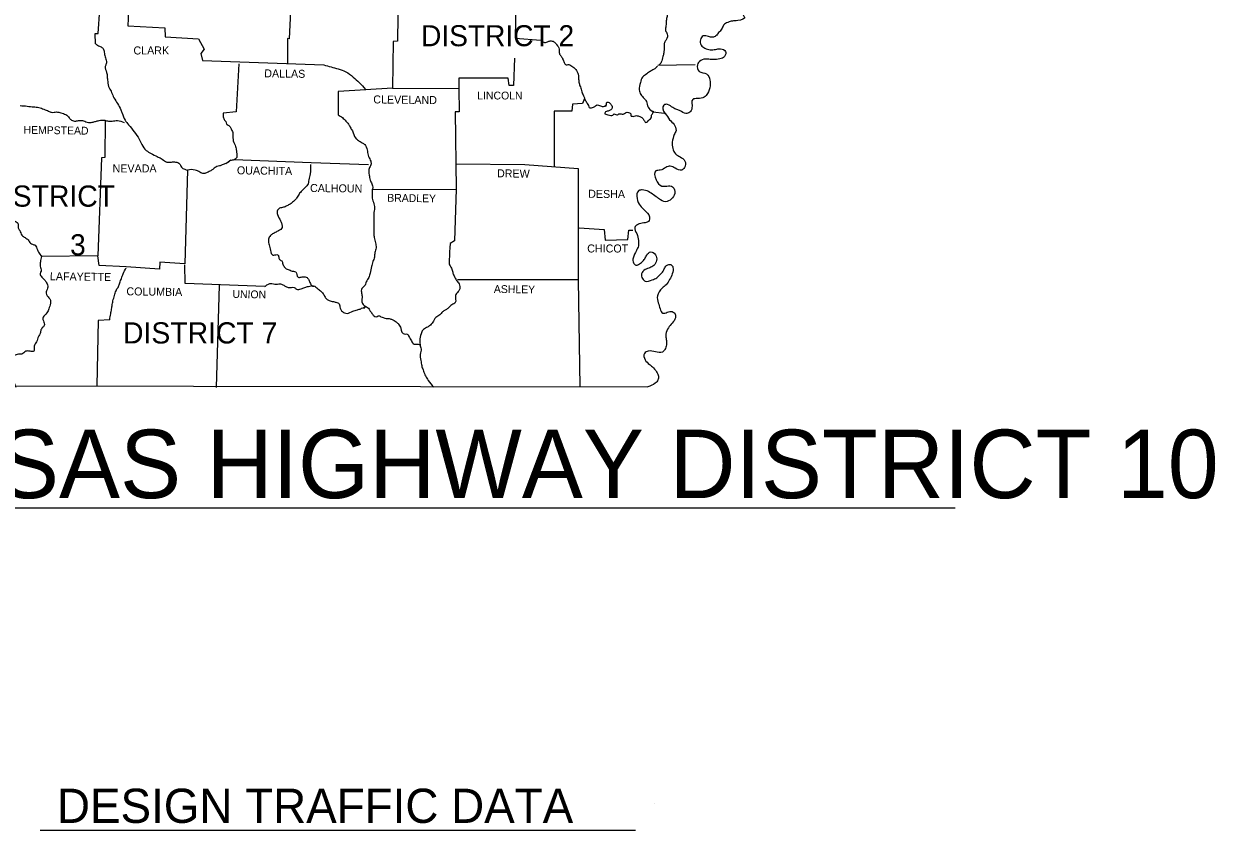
# Model space of a CAD drawing. Extents: x 152 to 3426, y 67 to 2142.
# Drawn here: x 2800 to 3426, y 1200 to 1624 of the extents above; entities that cross this region are included whole.
import ezdxf

# ---------------------------------------------------------------- set-up
doc = ezdxf.new("R2010")
doc.units = 0
for name, color, linetype in [('R_Border', 7, 'Continuous'), ('R_Grid', 7, 'Continuous'), ('S_AREA_CALC', 7, 'Continuous')]:
    doc.layers.add(name, color=color, linetype=linetype)

msp = doc.modelspace()

# ---------------------------------------------------------------- linework, layer by layer
at = {"layer": 'R_Grid'}
msp.add_line((3130.78, 1577.48), (3136.95, 1576.7), dxfattribs=at)
at = {"layer": 'S_AREA_CALC'}
for p, q in [((3133.42, 1601.94), (3152.99, 1602.24)), ((2625.16, 1369.37), (3289.7, 1369.37)), ((3131.43, 1213.84), (3131.43, 1213.84)), ((2808.55, 1199.86), (3121.64, 1199.86))]:
    msp.add_line(p, q, dxfattribs=at)
for points in [[(2997.03, 1654.09), (2996.45, 1614.56), (2994.2, 1614.47), (2993.9, 1589.91)], [(3059.06, 1653.99), (3058.28, 1616.13), (3071.88, 1615.05)], [(2940.68, 1641.37), (2939.5, 1615.74), (2938.62, 1616.03), (2938.72, 1602.72)], [(2837.65, 1613.19), (2837.46, 1618.57), (2839.02, 1618.67), (2840, 1631.29), (2855.07, 1630.32), (2854.68, 1622.59), (2874.15, 1621.51), (2874.24, 1616.81), (2891.85, 1615.74), (2894.89, 1610.45), (2893.03, 1608.11), (2893.91, 1604.49), (2957.7, 1602.14)], [(3057.99, 1605.66), (3057.4, 1591.28), (3055.15, 1591.28), (3054.76, 1595.09), (3028.73, 1595.09), (3028.73, 1589.61)], [(2913.09, 1602.63), (2911.62, 1577.48), (2904.87, 1576.7)], [(2979.81, 1589.03), (2965.33, 1588.15), (2965.24, 1575.92)], [(2993.9, 1589.91), (2979.62, 1589.03)], [(2993.9, 1589.91), (3028.54, 1589.71)], [(3028.73, 1589.71), (3028.83, 1577.48), (3026.78, 1577.38), (3027.36, 1536.78)], [(3094.87, 1584.53), (3093.7, 1581.88), (3088.51, 1581.4), (3088.22, 1577.87), (3078.93, 1577.87), (3078.83, 1548.62)], [(3105.83, 1580.22), (3106.13, 1580.51), (3106.42, 1580.81), (3106.42, 1580.81)], [(2842.84, 1572.98), (2842.64, 1553.51), (2840.88, 1553.31), (2838.92, 1501.75)], [(2910.64, 1552.34), (2951.15, 1550.87), (2981.18, 1549.69)], [(3027.07, 1550.09), (3063.37, 1549.79), (3091.55, 1547.64)], [(3091.55, 1547.64), (3091.55, 1489.13), (3092.33, 1432.87)], [(2885.98, 1546.86), (2884.71, 1497.55), (2871.5, 1498.43), (2871.41, 1494.81), (2853.79, 1495.88)], [(2983.14, 1536.68), (3027.36, 1536.78)], [(3027.36, 1536.78), (3026.39, 1509.58), (3024.23, 1508.21)], [(3092.04, 1516.43), (3105.15, 1515.65), (3105.73, 1509.97), (3117.57, 1510.36), (3118.06, 1515.16), (3120.31, 1515.16)], [(2769.26, 1512.61), (2769.46, 1433.46), (3128.04, 1432.87)], [(2853.79, 1495.88), (2839.61, 1496.67), (2838.92, 1501.75), (2809.28, 1501.46)], [(2926.69, 1485.61), (2884.91, 1487.17), (2884.71, 1497.06)], [(2902.72, 1486.29), (2901.15, 1432.58)], [(3027.95, 1489.23), (3091.55, 1489.23)], [(2845.18, 1468.19), (2839.12, 1467.8), (2838.43, 1433.36)]]:
    msp.add_lwpolyline(points, dxfattribs=at)
for points in [[(3210.42, 1697.14), (3208.17, 1694.3), (3204.85, 1696.06), (3204.85, 1698.41), (3205.34, 1700.86), (3204.16, 1702.42), (3202.11, 1701.74), (3202.11, 1698.71), (3201.91, 1695.77), (3201.32, 1691.56), (3202.69, 1690.29), (3205.83, 1689.9), (3208.08, 1689.31), (3209.45, 1687.06), (3209.35, 1684.32), (3208.27, 1681.68), (3206.71, 1679.53), (3204.26, 1678.75), (3202.3, 1680.02), (3201.52, 1682.56), (3200.64, 1684.81), (3198.98, 1686.48), (3197.22, 1684.62), (3196.82, 1681.19), (3196.92, 1678.26), (3196.92, 1674.25), (3199.47, 1671.6), (3201.03, 1668.57), (3200.54, 1665.83), (3198.68, 1662.6), (3197.9, 1659.77), (3197.12, 1655.95), (3197.22, 1651.74), (3196.53, 1647.63), (3195.16, 1644.89), (3192.62, 1642.64), (3190.95, 1641.18), (3189.58, 1639.71), (3188.9, 1636.77), (3188.41, 1634.72), (3186.55, 1632.27), (3185.08, 1632.08), (3183.91, 1633.05), (3183.52, 1634.72), (3183.52, 1636.38), (3182.74, 1638.04), (3180.29, 1638.73), (3178.33, 1638.63), (3177.45, 1637.26), (3178.72, 1633.45), (3179.21, 1631), (3178.53, 1627.67), (3178.92, 1627.28), (3175.4, 1625.42), (3172.56, 1625.13), (3170.21, 1624.44), (3167.96, 1622.98), (3166.88, 1620.82), (3165.32, 1619.06), (3163.95, 1617.4), (3162.09, 1616.62), (3160.04, 1617.01), (3157.3, 1617.3), (3155.73, 1615.35), (3156.22, 1612.51), (3158.08, 1610.85), (3160.82, 1610.06), (3163.66, 1610.26), (3166.4, 1610.55), (3168.94, 1609.18), (3168.45, 1606.54), (3166, 1605.27), (3162.38, 1604.88), (3159.45, 1605.17), (3155.93, 1604.39), (3154.17, 1602.14), (3155.14, 1598.71), (3158.96, 1597.34), (3160.72, 1594.11), (3160.82, 1591.08), (3159.55, 1587.07), (3157.79, 1585.21), (3154.36, 1584.43), (3151.72, 1583.94), (3151.33, 1579.44), (3150.15, 1577.19), (3148.1, 1576.5), (3145.16, 1577.97), (3143.4, 1578.66), (3141.25, 1579.63), (3138.51, 1581.3), (3136.46, 1581), (3137.04, 1576.7), (3137.24, 1576.5), (3139.59, 1573.27), (3141.94, 1570.73), (3143.01, 1567.7)], [(3109.06, 1665.64), (3109.35, 1661.62), (3111.7, 1661.04), (3112.68, 1659.96), (3113.17, 1657.71), (3114.83, 1656.73), (3117.08, 1655.36), (3118.45, 1654.38), (3119.43, 1652.82), (3120.02, 1650.27), (3121.58, 1648.61), (3123.74, 1647.83), (3125.3, 1645.97), (3126.28, 1643.33), (3127.85, 1642.15), (3129.41, 1640.1), (3130.19, 1639.22), (3131.56, 1636.87), (3132.93, 1635.7), (3133.91, 1635.01), (3135.48, 1634.52), (3137.43, 1633.25), (3138.71, 1631.29), (3138.71, 1629.83), (3138.22, 1627.58), (3137.83, 1625.23), (3137.63, 1622.59), (3137.43, 1620.24), (3138.32, 1618.28), (3137.83, 1615.35), (3136.85, 1613.78), (3136.75, 1611.63), (3136.46, 1608.4), (3136.07, 1606.54), (3135.18, 1603.51), (3133.91, 1601.94)], [(2837.65, 1613.19), (2839.22, 1612.21), (2841.08, 1611.33), (2842.05, 1609.87), (2842.45, 1607.62), (2843.13, 1605.17), (2843.33, 1602.63), (2842.74, 1601.26), (2843.52, 1598.13), (2843.82, 1595.97), (2844.11, 1593.43), (2844.89, 1590.01), (2846.16, 1587.66), (2847.34, 1584.82), (2849.29, 1581.79), (2850.96, 1578.46), (2851.74, 1576.7), (2853.21, 1573.08), (2855.07, 1570.63), (2858, 1566.91), (2860.64, 1563.1), (2862.11, 1560.26), (2864.36, 1557.13), (2866.91, 1555.57), (2870.13, 1553.9), (2872.19, 1552.92), (2874.54, 1551.26), (2877.57, 1551.06), (2879.82, 1551.06), (2881.88, 1550.18), (2882.85, 1548.42), (2884.61, 1547.25), (2885.98, 1546.86)], [(3071.88, 1615.05), (3073.35, 1614.07), (3075.4, 1614.17), (3076.77, 1614.76), (3077.85, 1614.66), (3079.32, 1613.78), (3080.3, 1612.61), (3080.98, 1611.73), (3081.47, 1610.36), (3081.47, 1609.08), (3081.96, 1607.32), (3082.55, 1606.64), (3083.33, 1605.37), (3083.82, 1604.19), (3084.11, 1603.41), (3085.19, 1602.14), (3086.17, 1602.24), (3087.05, 1602.14), (3088.22, 1601.45), (3089.98, 1600.08), (3090.28, 1599.69), (3091.45, 1597.15), (3091.65, 1595.58), (3091.84, 1593.53), (3092.23, 1591.57), (3093.02, 1589.42), (3093.41, 1587.95), (3094.29, 1585.9), (3094.87, 1584.53), (3095.66, 1582.76), (3096.83, 1580.81), (3097.32, 1579.63), (3098.98, 1579.73), (3100.16, 1580.22), (3101.04, 1581), (3102.11, 1580.91), (3103.29, 1580.51), (3104.85, 1580.22), (3105.83, 1580.81), (3106.32, 1581.2), (3106.42, 1582.08), (3107.3, 1582.57), (3108.28, 1581.88), (3109.35, 1580.32), (3109.35, 1579.34), (3108.96, 1578.75), (3107.69, 1577.97), (3105.93, 1577.38), (3105.44, 1576.7), (3107.1, 1575.92), (3109.75, 1575.72), (3110.43, 1576.31), (3112.19, 1575.82), (3112.88, 1576.31), (3115.23, 1576.21), (3116.3, 1576.99), (3118.45, 1576.89), (3119.14, 1576.41), (3119.14, 1575.52), (3120.9, 1575.13), (3122.17, 1575.43), (3123.84, 1574.94), (3125.3, 1574.15), (3126.09, 1573.08), (3127.06, 1571.9), (3127.94, 1572.2), (3128.63, 1573.08), (3130.1, 1574.64), (3130.1, 1575.62), (3130.49, 1576.31), (3130.98, 1577.29)], [(2957.7, 1602.14), (2965.33, 1599.98), (2969.25, 1598.52), (2973.16, 1595.68), (2976.39, 1592.84), (2979.62, 1589.22)], [(3133.23, 1601.35), (3131.17, 1599.69), (3129.41, 1598.71), (3127.55, 1597.34), (3125.3, 1595.68), (3124.23, 1592.84), (3123.64, 1588.93), (3124.42, 1586.58), (3126.18, 1584.53), (3127.36, 1582.86), (3128.24, 1579.93), (3130.39, 1577.87), (3131.08, 1577.58)], [(2798.03, 1580.71), (2801.74, 1580.42), (2805.17, 1580.03), (2807.81, 1579.73), (2810.55, 1578.75), (2813, 1577.87), (2814.56, 1577.19), (2817.2, 1577.38), (2819.45, 1576.89), (2822, 1576.01), (2823.86, 1574.35), (2825.03, 1573.08), (2827.28, 1572.59), (2829.14, 1572.88), (2831.39, 1572.69), (2833.93, 1571.9), (2835.99, 1572), (2837.65, 1572.39), (2839.61, 1572.88), (2842.05, 1573.08), (2843.91, 1572.69), (2846.36, 1572.59), (2849.2, 1572.88), (2852.72, 1571.9)], [(2904.87, 1576.7), (2904.87, 1574.84), (2905.55, 1573.08), (2906.24, 1572.3), (2906.53, 1571.02), (2907.41, 1570.44), (2908.68, 1569.26), (2909.37, 1567.6), (2909.86, 1566.52), (2909.86, 1565.15), (2909.96, 1563.78), (2910.15, 1562.12), (2911.33, 1559.19), (2911.62, 1558.01), (2911.81, 1557.03), (2911.91, 1555.37), (2911.91, 1553.41), (2910.64, 1552.34)], [(2965.24, 1575.92), (2967.49, 1574.45), (2969.34, 1572.49), (2970.71, 1571.02), (2971.59, 1569.36), (2972.77, 1567.4), (2974.43, 1563.69), (2975.9, 1562.41), (2977.95, 1561.14), (2979.23, 1560.26), (2980.5, 1557.42), (2981.09, 1554.59), (2982.16, 1552.04), (2982.65, 1550.09), (2981.77, 1548.13), (2981.57, 1544.22), (2982.16, 1541.57), (2982.94, 1539.62), (2983.43, 1537.37), (2983.14, 1536.68)], [(3143.01, 1567.7), (3142.03, 1565.45), (3140.96, 1561.53), (3141.25, 1558.21), (3142.72, 1555.37), (3145.07, 1553.8), (3147.61, 1551.55), (3147.41, 1548.13), (3145.95, 1546.86), (3142.52, 1547.74), (3139.88, 1548.91), (3137.63, 1548.23), (3134.6, 1546.76), (3132.35, 1546.47), (3132.45, 1541.77), (3135.48, 1538.44), (3138.12, 1538.44), (3141.15, 1538.05), (3142.23, 1534.53), (3140.47, 1531.59), (3137.53, 1530.13), (3133.81, 1531.89), (3131.17, 1533.75), (3128.53, 1535.51), (3125.2, 1536.39), (3123.35, 1536), (3122.47, 1531.89), (3124.03, 1528.17), (3126.57, 1525.63), (3128.92, 1522.3), (3128.53, 1519.85), (3126.77, 1519.17), (3123.64, 1518.48), (3121.78, 1517.51), (3121.29, 1516.72), (3122.27, 1513.4), (3123.15, 1509.78), (3123.15, 1507.04), (3122.07, 1504.49), (3120.41, 1500.58), (3120.61, 1498.03), (3121.78, 1496.86), (3123.25, 1497.25), (3125.2, 1498.62), (3126.48, 1500.19), (3127.55, 1502.14), (3129.61, 1503.81), (3132.15, 1502.34), (3132.74, 1499.31), (3131.27, 1496.67), (3129.22, 1495.49), (3126.67, 1494.51), (3124.81, 1492.36), (3125.3, 1489.82), (3126.77, 1488.45), (3130.39, 1489.13), (3132.84, 1490.21), (3134.21, 1491.58), (3135.87, 1493.24), (3136.75, 1494.9), (3138.02, 1496.67), (3140.27, 1497.15), (3141.35, 1495.69), (3140.96, 1492.36), (3139.59, 1489.23), (3137.73, 1486.59), (3135.67, 1484.73), (3133.13, 1480.72), (3133.62, 1477), (3134.6, 1473.97), (3135.97, 1471.62), (3138.32, 1472.11), (3140.96, 1472.4), (3142.52, 1471.13), (3142.33, 1468.39), (3140.37, 1465.75), (3138.51, 1463.2), (3137.53, 1459.68), (3137.92, 1457.24), (3137.92, 1454.98), (3137.14, 1452.54), (3135.77, 1451.17), (3132.15, 1451.27), (3128.34, 1451.66), (3126.28, 1450.48), (3126.67, 1447.16), (3128.92, 1444.71), (3130.49, 1443.44), (3132.74, 1440.7), (3133.72, 1438.45), (3133.42, 1436.49), (3132.05, 1434.83), (3128.04, 1432.87)], [(2908.78, 1551.95), (2906.24, 1550.28), (2904.28, 1549.5), (2902.81, 1549.01), (2901.44, 1548.62), (2899.68, 1547.44), (2898.31, 1546.47), (2896.45, 1545.59), (2894.69, 1545), (2892.54, 1545.68), (2891.37, 1546.37), (2890.09, 1546.86), (2885.98, 1546.86)], [(2906.24, 1550.28), (2908.78, 1551.95), (2910.64, 1552.34)], [(2950.75, 1549.69), (2950.56, 1544.8), (2949.87, 1541.77), (2949.19, 1539.03), (2947.72, 1537.46), (2946.16, 1535.9), (2944.69, 1534.14), (2943.42, 1531.99), (2942.14, 1530.62), (2940.48, 1529.25), (2938.82, 1528.27), (2936.96, 1527.39), (2934.9, 1526.9), (2933.44, 1525.82), (2933.34, 1523.47), (2935, 1520.15), (2935.59, 1518.58), (2935.79, 1516.72), (2935.1, 1515.65), (2933.53, 1514.77), (2931.68, 1513.69), (2930.01, 1512.71), (2928.84, 1511.05), (2928.64, 1508.8), (2929.43, 1506.16), (2929.72, 1504.59), (2930.99, 1502.14), (2931.97, 1502.24), (2933.73, 1502.14), (2933.93, 1501.65), (2934.02, 1501.17), (2934.42, 1499.89), (2935.88, 1498.82), (2936.08, 1497.84), (2936.96, 1495.98), (2938.43, 1494.71), (2939.5, 1494.32), (2941.75, 1493.63), (2942.93, 1493.34), (2944.2, 1490.5), (2945.77, 1490.6), (2946.94, 1490.79), (2948.9, 1490.31), (2949.78, 1489.13), (2950.66, 1487.17), (2951.83, 1485.8), (2952.61, 1485.8)], [(2983.14, 1536.68), (2983.53, 1530.62), (2984.41, 1527.68), (2984.12, 1524.55), (2984.02, 1521.52), (2984.02, 1518.78), (2984.02, 1516.14), (2984.02, 1513.4), (2984.22, 1511.44), (2984.9, 1508.6), (2985.19, 1505.96), (2984.61, 1503.42), (2984.31, 1501.07), (2983.53, 1498.72), (2982.85, 1496.08), (2982.06, 1492.65), (2981.38, 1490.4), (2980.01, 1488.06), (2979.13, 1485.9), (2977.76, 1484.53), (2977.56, 1482.18), (2977.86, 1480.03), (2977.66, 1478.08), (2978.35, 1476.22), (2980.11, 1474.94)], [(2769.26, 1512.61), (2772.68, 1514.08), (2774.15, 1513.59), (2775.42, 1512.32), (2776.89, 1512.32), (2777.67, 1513.49), (2779.14, 1513.59), (2780.32, 1513.49), (2781.59, 1514.28), (2782.66, 1514.77), (2784.13, 1515.25), (2785.21, 1515.65), (2786.19, 1516.72), (2787.95, 1517.6), (2790, 1518.29), (2790.59, 1519.27), (2791.57, 1519.66), (2793.52, 1519.56), (2794.8, 1520.15), (2795.87, 1519.66), (2796.85, 1518.97), (2797.05, 1516.43), (2797.83, 1515.06), (2799, 1512.61), (2800.67, 1511.34), (2802.23, 1510.07), (2802.82, 1509.29), (2804.48, 1507.82), (2805.95, 1507.33), (2806.64, 1506.25), (2807.71, 1503.71), (2809.28, 1501.46)], [(3024.23, 1508.21), (3023.94, 1505.18), (3023.84, 1502.34), (3023.65, 1499.6), (3023.65, 1497.55), (3024.82, 1495.3), (3025.51, 1493.14), (3026.19, 1491.28), (3027.56, 1488.84), (3028.83, 1486.98), (3029.22, 1484.34), (3028.44, 1482.97), (3026.97, 1480.91), (3026.87, 1477.19), (3025.11, 1476.02), (3022.86, 1474.06), (3021.59, 1473.18), (3020.22, 1472.3), (3018.75, 1470.74), (3016.6, 1469.27), (3015.04, 1466.82), (3013.28, 1464.96), (3011.81, 1463.99), (3009.75, 1462.71), (3008.87, 1460.76), (3008.19, 1457.14), (3008.48, 1454.5), (3008.87, 1452.15), (3008.38, 1449.21), (3008.87, 1445.98), (3009.36, 1443.44), (3010.14, 1441.19), (3011.22, 1438.65), (3012.59, 1436.3), (3015.53, 1432.68)], [(2809.28, 1501.46), (2808.69, 1498.62), (2808.59, 1496.37), (2809.08, 1493.73), (2808.59, 1492.46), (2809.38, 1490.6), (2810.84, 1489.13), (2811.92, 1487.57), (2812.6, 1485.32), (2811.72, 1482.77), (2812.7, 1480.13), (2813.58, 1479.15), (2814.07, 1477.59), (2813.39, 1474.55), (2812.51, 1472.3), (2810.55, 1470.05), (2809.96, 1468.98), (2810.26, 1467.51), (2810.74, 1465.16), (2810.26, 1464.48), (2808.98, 1462.81), (2808.59, 1460.95), (2807.71, 1459.39), (2806.73, 1456.55), (2805.46, 1454.2), (2805.27, 1451.56), (2803.31, 1451.56), (2801.06, 1451.56), (2799, 1450.09), (2797.15, 1450), (2794.89, 1449.11), (2793.52, 1447.26), (2793.04, 1445.2), (2792.45, 1443.24), (2793.04, 1439.92), (2793.92, 1437.57), (2794.6, 1435.71), (2795.78, 1432.68)], [(2845.18, 1468.19), (2845.67, 1471.32), (2846.16, 1473.77), (2846.46, 1476.12), (2847.04, 1478.76), (2847.92, 1481.6), (2848.71, 1483.95), (2849.78, 1485.61), (2850.47, 1487.57), (2851.35, 1489.91), (2852.23, 1492.36), (2853.79, 1495.49)], [(2926.69, 1485.61), (2928.25, 1486.69), (2929.72, 1487.27), (2931.19, 1486.98), (2932.75, 1486.78), (2934.12, 1486.98), (2935.88, 1486.69), (2937.35, 1485.8), (2939.01, 1485.12), (2940.68, 1485.12), (2942.14, 1485.12), (2943.42, 1484.24), (2945.77, 1484.34), (2947.72, 1485.12), (2949.68, 1485.71), (2952.32, 1486), (2954.67, 1484.34), (2956.33, 1482.97), (2957.7, 1481.4), (2958.68, 1479.64), (2959.76, 1478.66), (2961.52, 1477.98), (2962.89, 1477.68), (2964.55, 1477.19), (2965.43, 1476.8), (2966.21, 1474.94), (2967.49, 1472.4), (2969.93, 1471.52), (2972.96, 1472.69), (2975.41, 1473.38), (2977.17, 1473.97), (2978.25, 1474.36), (2979.23, 1474.46), (2978.93, 1474.65), (2980.11, 1474.94), (2981.18, 1474.16), (2981.87, 1473.09), (2983.04, 1471.52), (2984.12, 1470.15), (2985.19, 1469.66), (2986.27, 1470.25), (2987.74, 1469.76), (2989.01, 1469.27), (2990.48, 1468.88), (2991.75, 1468.78), (2993.41, 1468.39), (2994.69, 1467.7), (2995.86, 1467.02), (2997.03, 1465.75), (2998.21, 1463.79), (2998.6, 1462.23), (2999.97, 1460.66), (3001.24, 1460.66), (3003.1, 1458.12), (3003.78, 1457.14), (3005.25, 1455.38), (3006.33, 1455.38), (3008.38, 1454.98)]]:
    msp.add_spline(points, degree=3, dxfattribs=at)

# ---------------------------------------------------------------- texts
at = {"layer": 'R_Border'}
for s, height, p in [('CLARK', 4.207, (2857.63, 1607.59)), ('LINCOLN', 4.109, (3038.42, 1583.94)), ('NEVADA', 4.207, (2846.65, 1545.59)), ('CHICOT', 4.207, (3096.24, 1503.51)), ('ARKANSAS HIGHWAY DISTRICT 10', 36, (2620.5, 1374.37))]:
    msp.add_text(s, height=height, dxfattribs=at).set_placement(p)
for s, height, rotation, p in [('DALLAS', 4.206, 359.24615, (2926.39, 1595.58)), ('CLEVELAND', 4.207, 359.33765, (2983.73, 1581.88)), ('HEMPSTEAD', 4.108, 359.1885, (2799.79, 1565.94)), ('OUACHITA', 4.207, 359.20428, (2912.01, 1544.61)), ('DREW', 4.206, 359.22578, (3048.79, 1543.04)), ('CALHOUN', 4.207, 359.36341, (2950.46, 1535.31)), ('DESHA', 4.206, 359.3704, (3096.73, 1532.28)), ('BRADLEY', 4.108, 359.1449, (2991.07, 1530.22)), ('LAFAYETTE', 4.206, 359.18388, (2813.68, 1488.94)), ('COLUMBIA', 4.206, 359.21248, (2853.89, 1481.01)), ('ASHLEY', 4.109, 359.2361, (3047.13, 1482.28)), ('UNION', 4.109, 358.95837, (2909.66, 1479.64))]:
    msp.add_text(s, height=height, rotation=rotation, dxfattribs=at).set_placement(p)
at = {"layer": 'R_Grid'}
for s, height, p in [('DISTRICT 2', 11.056, (3008.87, 1611.92)), ('DISTRICT', 11.154, (2779.19, 1527.57)), ('3', 11.06, (2824.3, 1502.04)), ('DISTRICT 7', 11.154, (2852.13, 1455.67))]:
    msp.add_text(s, height=height, dxfattribs=at).set_placement(p)
at = {"layer": 'S_AREA_CALC'}
msp.add_text('DESIGN TRAFFIC DATA', height=18, dxfattribs=at).set_placement((2817.4, 1203.67))

doc.saveas('drawing.dxf')
